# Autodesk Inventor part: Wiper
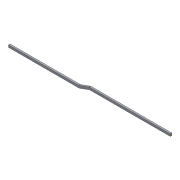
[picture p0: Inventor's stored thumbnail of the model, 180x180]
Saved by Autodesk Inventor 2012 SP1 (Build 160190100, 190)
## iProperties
Created: 2006-03
Part Number: Wiper
Document SubType Name: Modeling
Material: Stainless Steel, 440C
Mass: 28.0148 g
Surface Area: 42.4106 cm^2
Volume: 3.61481 cm^3
Density: 7.75 g/cm^3
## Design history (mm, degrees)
sketch "Sketch1"
  geometry: L1 (-1.5, 2)-(1.5, 2); L2 (1.5, 2)-(1.5, -2); L3 (1.5, -2)-(-1.5, -2); L4 (-1.5, -2)-(-1.5, 2); L5 (-1.5, 2)-(1.5, -2); 2 further points
  constraints: 10 end point, 2 parallel, 1 coincident, 1 horizontal, 1 midpoint, 1 perpendicular
  dimensions: "d0" = 3 distance of L1.start L1.end; "d1" = 4 distance of L3.end L1.start
sketch "Sketch2"
  geometry: L1 (0, 0)-(150, 0); L2 (150, 0)-(169.232, -7); L3 (169.232, -7)-(300, -7)
  constraints: 6 end point, 1 horizontal, 1 parallel
  dimensions: "d2" = 150 distance of L1.start L1.end; "d3" = 160 deg angle of L2 L1; "d4" = 300 horizontal distance of L3.end L1.start; "d5" = 7 distance between parallel lines of L3 L1
sweep "Sweep1" sketch "Sketch1", "Sketch2" dims "d6" = 0
fillet "Fillet1" dims "d7" = 5
workaxis "Work Axis1"
workaxis "Work Axis2"
body "Solid1"
